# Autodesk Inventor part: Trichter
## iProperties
Created: 2010-10
Part Number: Trichter
Material: 1.4301
Document SubType Name: Blech
Designer: Tim Müller
Density: 7.9 g/cm^3
Flat Pattern Width: 168.799 cm
Flat Pattern Length: 135.573 cm
Flat Pattern Area: 22884.6 cm^2
Sheet Metal Rule: 14301_1,5mm
Author: Tim Müller
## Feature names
1. Biegung1
